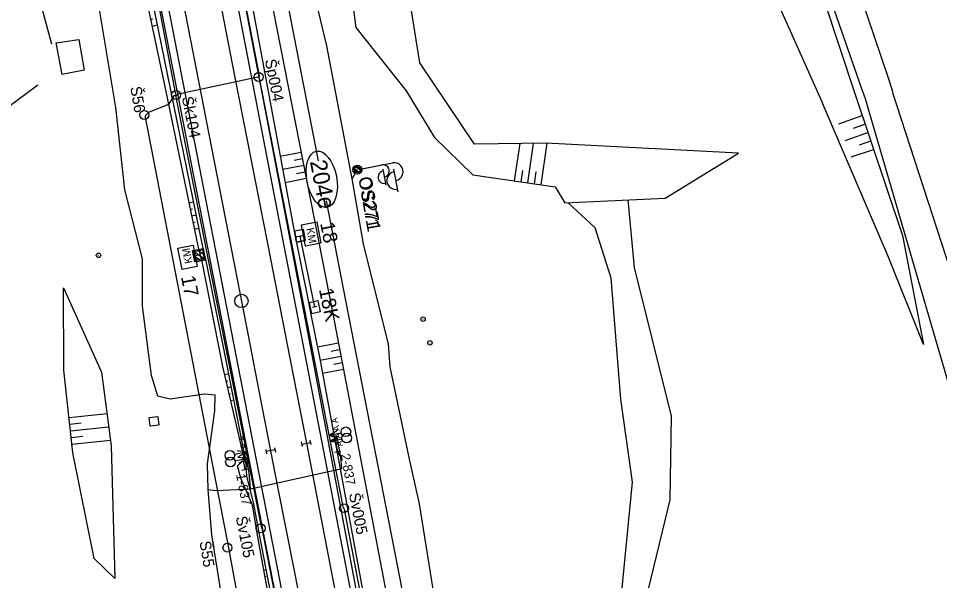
# Model space of a CAD drawing. Extents: x -545967 to -545044, y -1122650 to -1118491.
# Drawn here: x -545860.5 to -545757.1, y -1118624.1 to -1118561 of the extents above; entities that cross this region are included whole.
import ezdxf

# ---------------------------------------------------------------- set-up
doc = ezdxf.new("R2010")
doc.units = 0
for name, color, linetype in [('Vrstva 1', 7, 'Continuous'), ('Vrstva 1 - Koleje', 7, 'Continuous'), ('Vrstva 11 - Trakce', 7, 'Continuous'), ('Vrstva 12 - Trakce zaklady', 7, 'Continuous'), ('Vrstva 19 - Staniceni', 7, 'Continuous'), ('Vrstva 2', 7, 'Continuous'), ('Vrstva 25', 7, 'Continuous'), ('Vrstva 25 - silnoproud prvky', 7, 'Continuous'), ('Vrstva 26', 7, 'Continuous'), ('Vrstva 26 - silnoproud', 7, 'Continuous'), ('Vrstva 28 - zabzar', 7, 'Continuous'), ('Vrstva 3 - Lisy - Pocitaci body', 7, 'Continuous'), ('Vrstva 32', 7, 'Continuous'), ('Vrstva 35', 7, 'Continuous'), ('Vrstva 4 - Teren - stezky - prechody - plochy', 7, 'Continuous'), ('Vrstva 41', 7, 'Continuous'), ('Vrstva 43', 7, 'Continuous'), ('Vrstva 44', 7, 'Continuous'), ('Vrstva 48', 7, 'Continuous'), ('Vrstva 49', 7, 'Continuous'), ('Vrstva 50', 7, 'Continuous'), ('Vrstva 51', 7, 'Continuous'), ('Vrstva 6 - Navesti', 7, 'Continuous'), ('Vrstva 62', 7, 'Continuous')]:
    doc.layers.add(name, color=color, linetype=linetype)

msp = doc.modelspace()

# ---------------------------------------------------------------- linework, layer by layer
at = {"layer": 'Vrstva 1'}
for points in [[(-545837.37, -1118522.82), (-545831.2, -1118554.49), (-545826.81, -1118577.01)], [(-545825.93, -1118581.52), (-545824.02, -1118591.36), (-545817.1, -1118626.81), (-545815.58, -1118634.58), (-545810.8, -1118659.2), (-545810.53, -1118660.55), (-545805.87, -1118684.41), (-545803.34, -1118697.36)]]:
    msp.add_lwpolyline(points, dxfattribs=at)
msp.add_ellipse((-545826.41, -1118579.08), major_axis=(0.61, -3.15), ratio=0.521067, dxfattribs=at)
at = {"layer": 'Vrstva 1 - Koleje'}
for points in [[(-545848.63, -1118525.02), (-545847.32, -1118531.71), (-545846.1, -1118538), (-545844.17, -1118547.96), (-545842.34, -1118557.29), (-545840.54, -1118566.52), (-545838.78, -1118575.54), (-545836.61, -1118586.68), (-545834.86, -1118595.65), (-545833.09, -1118604.76), (-545832.15, -1118609.56), (-545831.33, -1118613.78), (-545829.45, -1118623.42), (-545827.68, -1118632.5), (-545825.51, -1118643.64), (-545823.56, -1118653.59), (-545821.82, -1118662.54), (-545819.92, -1118672.31), (-545817.99, -1118682.17), (-545816.18, -1118691.47), (-545814.43, -1118700.43), (-545812.52, -1118710.22), (-545810.75, -1118719.32)], [(-545844.61, -1118524.24), (-545843.32, -1118530.85), (-545841.99, -1118537.67), (-545840.06, -1118547.59), (-545838.15, -1118557.39), (-545836.19, -1118567.48), (-545834.29, -1118577.17), (-545832.14, -1118588.19), (-545830.34, -1118597.44), (-545828.85, -1118605.08), (-545828.14, -1118608.72), (-545827.12, -1118613.94), (-545825.27, -1118623.44), (-545823.27, -1118633.72), (-545821.49, -1118642.86), (-545818.72, -1118657.02), (-545817.48, -1118663.39), (-545815.84, -1118671.8), (-545813.8, -1118682.29), (-545812, -1118691.52), (-545809.67, -1118703.45), (-545807.88, -1118712.63)]]:
    msp.add_lwpolyline(points, dxfattribs=at)
at = {"layer": 'Vrstva 11 - Trakce'}
for p, q in [((-545829.47, -1118585.08), (-545829.28, -1118586.07)), ((-545828.49, -1118584.89), (-545828.3, -1118585.87)), ((-545828.39, -1118585.38), (-545829.38, -1118585.57)), ((-545828.88, -1118585.48), (-545827.22, -1118593.43)), ((-545840.26, -1118587.1), (-545839.72, -1118587.47)), ((-545840.78, -1118587.2), (-545839.62, -1118587.99)), ((-545840.69, -1118587.72), (-545840.13, -1118588.1)), ((-545826.97, -1118593.37), (-545827.46, -1118593.48))]:
    msp.add_line(p, q, dxfattribs=at)
msp.add_lwpolyline([(-545839.8, -1118587.02), (-545839.62, -1118588), (-545840.6, -1118588.18), (-545840.78, -1118587.2)], close=True, dxfattribs=at)
at = {"layer": 'Vrstva 12 - Trakce zaklady'}
for p, q in [((-545829.49, -1118584.86), (-545828.51, -1118584.67)), ((-545829.24, -1118586.16), (-545828.26, -1118585.97)), ((-545840.92, -1118587.07), (-545839.74, -1118586.85)), ((-545840.67, -1118588.35), (-545839.5, -1118588.12)), ((-545827.83, -1118592.9), (-545826.85, -1118592.69)), ((-545826.58, -1118593.97), (-545827.56, -1118594.17))]:
    msp.add_line(p, q, dxfattribs=at)
for points in [[(-545829.24, -1118586.16), (-545829.49, -1118584.86), (-545828.51, -1118584.67), (-545828.26, -1118585.97), (-545829.24, -1118586.16)], [(-545829.49, -1118584.86), (-545829.49, -1118584.86), (-545829.24, -1118586.16), (-545829.24, -1118586.16)], [(-545839.74, -1118586.85), (-545839.5, -1118588.12), (-545840.67, -1118588.35), (-545840.92, -1118587.07), (-545839.74, -1118586.85)], [(-545840.92, -1118587.07), (-545840.92, -1118587.07), (-545840.67, -1118588.35), (-545840.67, -1118588.35)], [(-545839.74, -1118586.85), (-545839.74, -1118586.85), (-545839.5, -1118588.12), (-545839.5, -1118588.12)], [(-545827.56, -1118594.17), (-545827.83, -1118592.9), (-545826.85, -1118592.69), (-545826.58, -1118593.97), (-545827.56, -1118594.17)], [(-545827.83, -1118592.9), (-545827.83, -1118592.9), (-545827.56, -1118594.17), (-545827.56, -1118594.17)], [(-545826.85, -1118592.69), (-545826.85, -1118592.69), (-545826.58, -1118593.97), (-545826.58, -1118593.97)]]:
    msp.add_lwpolyline(points, dxfattribs=at)
at = {"layer": 'Vrstva 19 - Staniceni'}
for p, q in [((-545828.88, -1118585.48), (-545828.46, -1118585.4)), ((-545840.2, -1118587.6), (-545840.63, -1118587.68))]:
    msp.add_line(p, q, dxfattribs=at)
for points in [[(-545828.69, -1118584.2), (-545826.98, -1118583.87), (-545826.52, -1118586.27), (-545828.23, -1118586.6)], [(-545840.4, -1118588.88), (-545842.1, -1118589.21), (-545842.57, -1118586.82), (-545840.86, -1118586.48)]]:
    msp.add_lwpolyline(points, close=True, dxfattribs=at)
msp.add_circle((-545835.43, -1118592.74), 0.75, dxfattribs=at)
at = {"layer": 'Vrstva 25'}
for p, q in [((-545822.88, -1118577.85), (-545822.09, -1118578.39)), ((-545822.64, -1118577.56), (-545821.91, -1118578.05)), ((-545821.92, -1118577.91), (-545818.48, -1118577.25)), ((-545818.35, -1118577.94), (-545817.86, -1118580.49)), ((-545851.47, -1118587.64), (-545851.48, -1118587.59))]:
    msp.add_line(p, q, dxfattribs=at)
for centre, radius in [((-545822.41, -1118578), 0.5), ((-545822.41, -1118578), 0.5), ((-545851.47, -1118587.62), 0.25)]:
    msp.add_circle(centre, radius, dxfattribs=at)
for centre, start, end in [((-545818.29, -1118578.23), 280.8572, 100.8572), ((-545818.11, -1118579.22), 100.1546, 281.5597)]:
    msp.add_arc(centre, 1, start, end, dxfattribs=at)
at = {"layer": 'Vrstva 25 - silnoproud prvky'}
for p, q in [((-545822.57, -1118577.69), (-545822.06, -1118578.04)), ((-545822.06, -1118577.94), (-545819.66, -1118577.48)), ((-545822.74, -1118577.9), (-545822.18, -1118578.27)), ((-545819.56, -1118577.96), (-545819.22, -1118579.74))]:
    msp.add_line(p, q, dxfattribs=at)
msp.add_circle((-545822.41, -1118578), 0.35, dxfattribs=at)
for centre, start, end in [((-545819.53, -1118578.16), 280.8572, 100.8572), ((-545819.4, -1118578.85), 100.1546, 281.5597)]:
    msp.add_arc(centre, 0.7, start, end, dxfattribs=at)
at = {"layer": 'Vrstva 26'}
for points in [[(-545813.6, -1118626.95), (-545815.44, -1118615.53), (-545816.55, -1118610.49), (-545818.72, -1118600.14), (-545818.93, -1118597.59), (-545821.71, -1118586.34), (-545822.99, -1118579.03), (-545825.85, -1118564.11), (-545827.03, -1118559.14), (-545827.82, -1118554.5), (-545829.84, -1118544.12), (-545830.51, -1118540.06), (-545832.39, -1118529.05), (-545832.37, -1118528.93), (-545832.37, -1118528.33)], [(-545822.99, -1118579.03), (-545822.41, -1118578)]]:
    msp.add_lwpolyline(points, dxfattribs=at)
at = {"layer": 'Vrstva 26 - silnoproud'}
for points in [[(-545813.6, -1118626.95), (-545815.44, -1118615.53), (-545816.55, -1118610.49), (-545818.72, -1118600.14), (-545818.93, -1118597.59), (-545821.71, -1118586.34), (-545822.99, -1118579.03), (-545825.85, -1118564.11), (-545827.03, -1118559.14), (-545827.82, -1118554.5), (-545829.84, -1118544.12), (-545830.51, -1118540.06), (-545832.39, -1118529.05), (-545832.37, -1118528.93), (-545832.37, -1118528.33)], [(-545822.99, -1118579.03), (-545822.41, -1118578)]]:
    msp.add_lwpolyline(points, dxfattribs=at)
at = {"layer": 'Vrstva 28 - zabzar'}
for p, q in [((-545824.63, -1118609.65), (-545824.28, -1118610.26)), ((-545835.06, -1118611.65), (-545834.76, -1118611.06))]:
    msp.add_line(p, q, dxfattribs=at)
for points in [[(-545838.36, -1118603.32), (-545839.56, -1118603.21), (-545843.44, -1118603.76), (-545844.8, -1118603.42), (-545845.54, -1118601.1), (-545846.54, -1118593.34), (-545846.55, -1118588.02), (-545848.5, -1118580.25), (-545849.52, -1118571.04), (-545851.83, -1118557.06), (-545853.76, -1118547.62), (-545855.54, -1118541.31), (-545856.15, -1118534.49), (-545857.22, -1118526.7)], [(-545825.23, -1118696.09), (-545825.62, -1118693.58), (-545825.98, -1118691.23), (-545826.08, -1118690.61), (-545827.72, -1118683.66), (-545828.55, -1118678.72), (-545828.78, -1118674.2), (-545831.46, -1118657.27), (-545836.43, -1118633.48), (-545838.77, -1118619), (-545839.17, -1118613.92), (-545839.25, -1118611.04), (-545838.43, -1118605.08), (-545838.36, -1118603.32)], [(-545825.6, -1118607.8), (-545824.66, -1118608.19), (-545825.51, -1118608.49)], [(-545839.17, -1118613.92), (-545838.25, -1118614.01), (-545834.43, -1118613.83), (-545824.15, -1118611.55), (-545824.28, -1118610.26), (-545824.66, -1118608.19)], [(-545834.84, -1118609.7), (-545835.19, -1118610.02), (-545834.77, -1118610.44)], [(-545834.43, -1118613.83), (-545834.55, -1118612.01), (-545834.76, -1118611.06), (-545835.19, -1118610.02)]]:
    msp.add_lwpolyline(points, dxfattribs=at)
at = {"layer": 'Vrstva 3 - Lisy - Pocitaci body'}
for p, q in [((-545825.6, -1118607.8), (-545824.65, -1118607.26)), ((-545825.6, -1118607.8), (-545824.25, -1118607.54)), ((-545825.6, -1118607.8), (-545824.52, -1118607.94)), ((-545828.58, -1118609.06), (-545828.68, -1118608.57)), ((-545828.63, -1118608.81), (-545827.65, -1118608.62)), ((-545827.6, -1118608.87), (-545827.7, -1118608.38)), ((-545825.51, -1118608.49), (-545824.56, -1118607.95)), ((-545825.51, -1118608.49), (-545824.16, -1118608.23)), ((-545825.51, -1118608.49), (-545824.43, -1118608.63)), ((-545834.84, -1118609.7), (-545836.19, -1118609.96)), ((-545834.84, -1118609.7), (-545835.92, -1118609.56)), ((-545834.84, -1118609.7), (-545835.79, -1118610.24)), ((-545832.69, -1118609.41), (-545832.6, -1118609.9)), ((-545831.66, -1118609.46), (-545832.64, -1118609.65)), ((-545831.71, -1118609.22), (-545831.61, -1118609.71)), ((-545834.77, -1118610.44), (-545836.12, -1118610.71)), ((-545834.77, -1118610.44), (-545835.85, -1118610.3)), ((-545834.77, -1118610.44), (-545835.72, -1118610.98))]:
    msp.add_line(p, q, dxfattribs=at)
for centre in [(-545823.71, -1118607.43), (-545823.62, -1118608.12), (-545836.73, -1118610.07), (-545836.66, -1118610.81)]:
    msp.add_circle(centre, 0.542, dxfattribs=at)
at = {"layer": 'Vrstva 32'}
msp.add_lwpolyline([(-545836.43, -1118633.48), (-545838.77, -1118619), (-545839.17, -1118613.92), (-545839.25, -1118611.04), (-545838.43, -1118605.08), (-545838.36, -1118603.32), (-545839.56, -1118603.21), (-545843.44, -1118603.76), (-545844.8, -1118603.42), (-545845.54, -1118601.1), (-545846.54, -1118593.34), (-545846.55, -1118588.02), (-545848.5, -1118580.25), (-545849.52, -1118571.04), (-545851.83, -1118557.06), (-545853.76, -1118547.62), (-545855.54, -1118541.31), (-545856.15, -1118534.49), (-545857.22, -1118526.7)], dxfattribs=at)
at = {"layer": 'Vrstva 35'}
msp.add_line((-545834.43, -1118613.83), (-545824.15, -1118611.55), dxfattribs=at)
at = {"layer": 'Vrstva 4 - Teren - stezky - prechody - plochy'}
for points in [[(-545842.99, -1118523.92), (-545841.7, -1118530.4), (-545836.85, -1118554.45), (-545831.05, -1118584.6), (-545819.35, -1118645.26), (-545811.23, -1118686.91), (-545799.53, -1118746.65), (-545788.53, -1118802.77), (-545777.85, -1118857.7), (-545765.83, -1118919.34), (-545755.98, -1118970.18), (-545745.51, -1119023.12), (-545734.81, -1119078.88), (-545723.15, -1119138.68), (-545711.33, -1119199.26), (-545707.51, -1119218.93), (-545706.35, -1119218.8)], [(-545842.06, -1118523.74), (-545841.08, -1118528.8), (-545840.28, -1118532.87), (-545839.9, -1118534.49), (-545835.95, -1118554.69), (-545830.17, -1118584.85), (-545827.4, -1118599.38), (-545819.67, -1118640.63), (-545818.68, -1118644.83), (-545817.56, -1118652.41), (-545817.15, -1118653.25), (-545814.79, -1118664.65), (-545810.72, -1118686.2), (-545798.47, -1118747.29), (-545787.71, -1118802.92), (-545777.14, -1118857.58)], [(-545711.32, -1119247.44), (-545711.9, -1119243.96), (-545720.22, -1119201.67), (-545721.28, -1119195.76), (-545731.55, -1119141.71), (-545737.08, -1119112.42), (-545743.44, -1119079.1), (-545754.28, -1119022.01), (-545764.13, -1118971.24), (-545774.7, -1118917.12), (-545786.1, -1118858.18), (-545797, -1118803.41), (-545807.66, -1118749.42), (-545819.91, -1118686.43), (-545828.53, -1118641.36), (-545850.15, -1118530.53), (-545851.16, -1118525.52)], [(-545710.22, -1119247.22), (-545719, -1119201.39), (-545730.62, -1119141.39), (-545736.21, -1119112.21), (-545742.56, -1119078.93), (-545753.41, -1119021.81), (-545763.36, -1118970.94), (-545773.92, -1118916.71), (-545785.33, -1118858.19), (-545796.21, -1118802.91), (-545806.84, -1118748.63), (-545819.21, -1118686.19), (-545827.82, -1118641.01), (-545849.34, -1118530.25), (-545850.41, -1118525.37)]]:
    msp.add_lwpolyline(points, dxfattribs=at)
at = {"layer": 'Vrstva 41'}
msp.add_lwpolyline([(-545844.81, -1118605.7), (-545844.7, -1118606.7), (-545845.69, -1118606.8), (-545845.8, -1118605.81), (-545844.81, -1118605.7)], dxfattribs=at)
at = {"layer": 'Vrstva 43'}
msp.add_lwpolyline([(-545856.21, -1118563.78), (-545853.7, -1118563.39), (-545853.07, -1118566.85), (-545855.56, -1118567.31)], close=True, dxfattribs=at)
for centre in [(-545833.49, -1118567.6), (-545842.77, -1118569.62), (-545846.33, -1118571.86), (-545823.92, -1118616), (-545833.27, -1118618.27), (-545837, -1118620.44)]:
    msp.add_circle(centre, 0.5, dxfattribs=at)
at = {"layer": 'Vrstva 44'}
for points in [[(-545841.88, -1118523.7), (-545833.45, -1118567.46), (-545833.58, -1118567.61)], [(-545851.15, -1118525.52), (-545842.86, -1118569.39), (-545842.75, -1118569.69)], [(-545833.58, -1118567.61), (-545842.48, -1118569.52), (-545842.75, -1118569.69)], [(-545823.99, -1118615.97), (-545824, -1118615.83), (-545833.41, -1118567.73), (-545833.58, -1118567.61)], [(-545842.75, -1118569.69), (-545843.02, -1118569.71), (-545843.62, -1118570.7), (-545845.8, -1118571.54), (-545846.22, -1118571.98)], [(-545833.15, -1118618.24), (-545842.75, -1118569.87), (-545842.75, -1118569.69)], [(-545846.22, -1118571.98), (-545846.22, -1118572.12), (-545836.89, -1118620.47), (-545827.98, -1118669.16), (-545827.81, -1118669.46), (-545827.87, -1118669.73), (-545818.62, -1118716.33), (-545818.55, -1118716.8), (-545818.47, -1118717.2), (-545808.91, -1118765.43), (-545808.83, -1118765.88), (-545808.74, -1118766.38), (-545799.37, -1118814.75), (-545799.3, -1118815), (-545799.29, -1118815.32), (-545789.93, -1118863.75)], [(-545823.99, -1118615.97), (-545823.91, -1118616.11), (-545814.59, -1118665.11), (-545823.54, -1118666.51), (-545823.78, -1118666.53)], [(-545833.15, -1118618.24), (-545828.36, -1118642.96), (-545827.52, -1118644.18), (-545826.94, -1118646.98), (-545827.13, -1118648.76), (-545823.92, -1118666.28), (-545823.78, -1118666.53)]]:
    msp.add_lwpolyline(points, dxfattribs=at)
at = {"layer": 'Vrstva 48'}
for p, q in [((-545845.6, -1118561.14), (-545845.36, -1118561.09)), ((-545845.45, -1118561.88), (-545844.84, -1118561.75)), ((-545804.76, -1118579.27), (-545804.16, -1118575.08)), ((-545803.28, -1118579.49), (-545802.64, -1118575.06)), ((-545801.79, -1118579.7), (-545801.12, -1118575.04)), ((-545828.72, -1118576.07), (-545831.07, -1118576.53)), ((-545828.58, -1118576.8), (-545829.52, -1118576.99)), ((-545828.44, -1118577.54), (-545830.79, -1118578)), ((-545828.29, -1118578.28), (-545829.24, -1118578.46)), ((-545804.02, -1118579.38), (-545803.83, -1118578.09)), ((-545802.54, -1118579.6), (-545802.34, -1118578.23)), ((-545828.15, -1118579.01), (-545830.52, -1118579.48)), ((-545841.29, -1118581.72), (-545840.79, -1118581.62)), ((-545841.13, -1118582.45), (-545840.94, -1118582.41)), ((-545840.98, -1118583.19), (-545840.5, -1118583.09)), ((-545840.83, -1118583.92), (-545840.63, -1118583.88)), ((-545840.67, -1118584.66), (-545840.2, -1118584.56)), ((-545824.55, -1118597.49), (-545826.9, -1118597.94)), ((-545824.41, -1118598.23), (-545825.34, -1118598.41)), ((-545824.27, -1118598.96), (-545826.6, -1118599.41)), ((-545823.98, -1118600.44), (-545826.33, -1118600.89)), ((-545824.13, -1118599.7), (-545825.06, -1118599.88)), ((-545837.31, -1118601), (-545836.85, -1118600.89)), ((-545837.14, -1118601.73), (-545836.96, -1118601.69)), ((-545836.97, -1118602.46), (-545836.56, -1118602.36)), ((-545836.8, -1118603.19), (-545836.64, -1118603.15)), ((-545836.63, -1118603.92), (-545836.27, -1118603.84)), ((-545854.78, -1118605.83), (-545850.52, -1118605.37)), ((-545854.7, -1118606.58), (-545853.42, -1118606.44)), ((-545854.62, -1118607.32), (-545850.33, -1118606.86)), ((-545854.54, -1118608.07), (-545853.25, -1118607.93)), ((-545854.46, -1118608.81), (-545850.14, -1118608.35)), ((-545832.91, -1118622.93), (-545832.64, -1118622.89)), ((-545832.78, -1118623.67), (-545832.67, -1118623.65))]:
    msp.add_line(p, q, dxfattribs=at)
at = {"layer": 'Vrstva 49'}
msp.add_line((-545827.54, -1118524.75), (-545822.58, -1118562.03), dxfattribs=at)
for points in [[(-545785.78, -1118514.97), (-545781.99, -1118523.73), (-545775.25, -1118543.19), (-545766.59, -1118569.47)], [(-545779.62, -1118576.17), (-545801.25, -1118575.04), (-545809.25, -1118575.15), (-545815.39, -1118566.01), (-545818.68, -1118545.33), (-545821.6, -1118525.57), (-545823.74, -1118522)], [(-545841.46, -1118523.62), (-545840.5, -1118528.8), (-545840.21, -1118530.17), (-545839.52, -1118532.72), (-545839.26, -1118534.26), (-545835.12, -1118554.72), (-545829.51, -1118584.89), (-545827.92, -1118592.87), (-545827.65, -1118594.26), (-545826.63, -1118599.22), (-545819.03, -1118640.37), (-545818.68, -1118644.83), (-545817.56, -1118652.41), (-545816.51, -1118653.06), (-545813.95, -1118664.57), (-545810.05, -1118684.98), (-545808.76, -1118691.23), (-545797.46, -1118748.58), (-545797, -1118749.95), (-545786.9, -1118802.73), (-545785.57, -1118809.02), (-545776.46, -1118857.74)], [(-545839.31, -1118523.2), (-545838.1, -1118529.58), (-545837.4, -1118533.49), (-545832.71, -1118555.7), (-545825.14, -1118594.38), (-545814.25, -1118651.35), (-545808.03, -1118685.15), (-545795.16, -1118750.19), (-545783.94, -1118809.71), (-545774.85, -1118856.95), (-545763.42, -1118915.04), (-545752.93, -1118968.66), (-545741.71, -1119025.95), (-545730.22, -1119081.99), (-545719, -1119141.33), (-545708.86, -1119196.83), (-545704.64, -1119214.15)], [(-545824.16, -1118671.87), (-545825.15, -1118666.55), (-545826.65, -1118657.26), (-545827.07, -1118653.96), (-545826.4, -1118653.65), (-545826.92, -1118650.89), (-545827.56, -1118650.88), (-545829.01, -1118644.14), (-545829.34, -1118642.71), (-545833.54, -1118619.46), (-545834.17, -1118615.67), (-545835.48, -1118612.65), (-545835.88, -1118611.24), (-545835.09, -1118610.53), (-545837.51, -1118600.11), (-545839.84, -1118588.3), (-545840.2, -1118586.92), (-545843.93, -1118569.06), (-545846.96, -1118554.73), (-545851.16, -1118532.2), (-545851.5, -1118530.84), (-545852.14, -1118525.71)], [(-545824.16, -1118671.87), (-545824.44, -1118666.47), (-545825.98, -1118657.27), (-545826.46, -1118654.02), (-545826.29, -1118653.73), (-545826.83, -1118650.74), (-545827.16, -1118650.61), (-545827.19, -1118650.51), (-545828.62, -1118644.06), (-545828.85, -1118642.68), (-545833.28, -1118619.55), (-545834.05, -1118615.55), (-545834.84, -1118612.36), (-545834.94, -1118610.69), (-545837.02, -1118600), (-545839.4, -1118588.22), (-545839.77, -1118586.66), (-545843.35, -1118569.09), (-545846.42, -1118554.05), (-545850.69, -1118532.2), (-545850.96, -1118530.82), (-545851.73, -1118525.63)], [(-545867.42, -1118528.7), (-545864.46, -1118533.89), (-545862.34, -1118543.35), (-545856.75, -1118563.89)], [(-545788.57, -1118529.43), (-545770.19, -1118570.55)], [(-545822.58, -1118562.03), (-545816.93, -1118569.17), (-545813.76, -1118574.4)], [(-545888.46, -1118583.33), (-545877.5, -1118577.84), (-545863.71, -1118572.5), (-545858.28, -1118568.48)], [(-545813.76, -1118574.4), (-545809.46, -1118578.59), (-545800.2, -1118579.94), (-545799.12, -1118581.74), (-545787.88, -1118581.2), (-545779.62, -1118576.17)], [(-545855.39, -1118591.26), (-545851.13, -1118600.73), (-545850.05, -1118609), (-545849.63, -1118623.9)], [(-545849.63, -1118623.9), (-545851.95, -1118621.64), (-545854.35, -1118609.8), (-545855.35, -1118600.5), (-545855.39, -1118591.26)], [(-545795.7, -1118699.53), (-545795.71, -1118697.62), (-545797.68, -1118680.08), (-545801.96, -1118672.21), (-545797.42, -1118652.76), (-545796.1, -1118641.45), (-545792.76, -1118625.71), (-545791.54, -1118613.07)]]:
    msp.add_lwpolyline(points, dxfattribs=at)
at = {"layer": 'Vrstva 50'}
for p, q in [((-545815.07, -1118594.78), (-545815.02, -1118594.78)), ((-545814.3, -1118597.44), (-545814.25, -1118597.44))]:
    msp.add_line(p, q, dxfattribs=at)
for centre in [(-545815.04, -1118594.78), (-545814.27, -1118597.44)]:
    msp.add_circle(centre, 0.25, dxfattribs=at)
at = {"layer": 'Vrstva 51'}
for points in [[(-545774.82, -1118543.07), (-545765.77, -1118569.1), (-545765.47, -1118569.91)], [(-545768.23, -1118551.74), (-545762.88, -1118567.59), (-545762.33, -1118569.21)]]:
    msp.add_lwpolyline(points, dxfattribs=at)
at = {"layer": 'Vrstva 6 - Navesti'}
for p, q in [((-545824.9, -1118608.29), (-545824.63, -1118609.65)), ((-545824.97, -1118609.72), (-545824.29, -1118609.58)), ((-545835.32, -1118610.29), (-545835.06, -1118611.65)), ((-545835.4, -1118611.72), (-545834.72, -1118611.58))]:
    msp.add_line(p, q, dxfattribs=at)
at = {"layer": 'Vrstva 62'}
for points in [[(-545766.59, -1118569.47), (-545761.22, -1118585.39), (-545758.87, -1118597.64), (-545762.78, -1118587.83), (-545770.19, -1118570.55)], [(-545720.18, -1118627.69), (-545733.85, -1118630.94), (-545738.3, -1118629.27), (-545742.37, -1118626.13), (-545745.34, -1118620.92), (-545748.3, -1118612.39), (-545762.34, -1118569.25)], [(-545765.47, -1118569.91), (-545752.75, -1118613.34), (-545745.62, -1118632.91), (-545739.77, -1118644.89), (-545732.31, -1118656.78), (-545724.88, -1118662.67), (-545709, -1118671.68)], [(-545765.8, -1118571.98), (-545768.42, -1118572.88)], [(-545765.48, -1118572.93), (-545766.77, -1118573.37)], [(-545765.15, -1118573.88), (-545767.71, -1118574.75)], [(-545764.51, -1118575.77), (-545767.01, -1118576.62)], [(-545764.83, -1118574.82), (-545766.09, -1118575.26)], [(-545791.54, -1118613.07), (-545792.86, -1118603.77), (-545793.91, -1118590.18), (-545795.71, -1118584.53), (-545798.76, -1118581.72)], [(-545792.04, -1118581.4), (-545791.33, -1118589), (-545787.18, -1118605.69), (-545787.34, -1118615.05), (-545790.08, -1118626.33)]]:
    msp.add_lwpolyline(points, dxfattribs=at)

# ---------------------------------------------------------------- texts
at = {"layer": 'Vrstva 11 - Trakce'}
for s, rotation, p in [('18', 281.0378, (-545826.6, -1118584.02)), ('17', 280.8153, (-545842.22, -1118590.03)), ('18K', 281.9566, (-545826.74, -1118591.45))]:
    msp.add_text(s, height=1.6, rotation=rotation, dxfattribs=at).set_placement(p)
at = {"layer": 'Vrstva 19 - Staniceni'}
for rotation, p in [(280.9198, (-545828.17, -1118584.62)), (100.9983, (-545840.92, -1118588.46))]:
    msp.add_text('KM', height=0.873, rotation=rotation, dxfattribs=at).set_placement(p)
at = {"layer": 'Vrstva 2'}
msp.add_text('204e', height=1.875, rotation=280.9117, dxfattribs=at).set_placement((-545827.75, -1118577.09))
at = {"layer": 'Vrstva 25'}
msp.add_text('OS271', height=1.5, rotation=279.9293, dxfattribs=at).set_placement((-545822.31, -1118578.92))
at = {"layer": 'Vrstva 25 - silnoproud prvky'}
msp.add_text('OS271', height=1.4, rotation=279.9293, dxfattribs=at).set_placement((-545822.31, -1118578.92))
at = {"layer": 'Vrstva 43'}
for s, rotation, p in [('Šp004', 280.9998, (-545832.8, -1118565.71)), ('Š56', 279.317, (-545847.91, -1118568.75)), ('Šk104', 280.9998, (-545842.12, -1118569.9)), ('Šv005', 280.9998, (-545823.37, -1118614.39)), ('Šv105', 280.9998, (-545836.07, -1118617.01)), ('Š55', 279.317, (-545840.14, -1118619.77))]:
    msp.add_text(s, height=1.25, rotation=rotation, dxfattribs=at).set_placement(p)
at = {"layer": 'Vrstva 6 - Navesti'}
for s, height, rotation, p in [('  A A A A ', 0.7, 101.0629, (-545823.94, -1118609.52)), ('  A A A A ', 0.7, 101.0176, (-545834.37, -1118611.52)), ('2-837', 1.05, 280.3814, (-545824.29, -1118609.98)), ('1-837', 1.05, 281.0176, (-545836.04, -1118612.23))]:
    msp.add_text(s, height=height, rotation=rotation, dxfattribs=at).set_placement(p)

doc.saveas('drawing.dxf')
